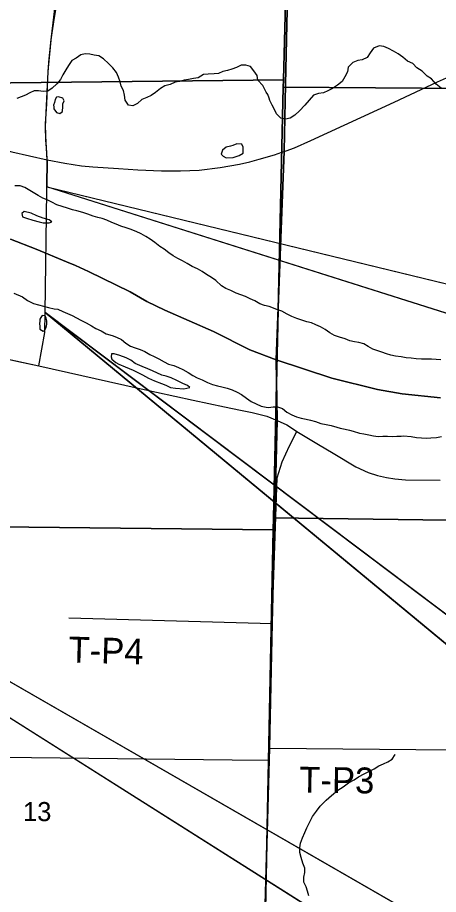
# Model space of a CAD drawing. Extents: x -6.2 to 37.4, y 0.2 to 22.2.
# Drawn here: x 6.554 to 7.016, y 18.086 to 19.048 of the extents above; entities that cross this region are included whole.
import ezdxf

# ---------------------------------------------------------------- set-up
doc = ezdxf.new("R2010")
doc.units = 0
for name, color, linetype in [('GM_X_County_Road', 7, 'Continuous'), ('GM_X_Major_River', 7, 'Continuous'), ('GM_X_Minor_Lake', 7, 'Continuous'), ('GM_X_Minor_River', 7, 'Continuous'), ('GM_X_Rail_Line', 7, 'Continuous'), ('GM_X_Section', 7, 'Continuous'), ('GM_X_Section_Text', 7, 'Continuous'), ('GM_X_State_Route', 7, 'Continuous'), ('GM_X_Township_Road', 7, 'Continuous'), ('GM_X_Township_Road_Text', 7, 'Continuous'), ('SH_Border', 7, 'Continuous'), ('SH_Data', 7, 'Continuous')]:
    doc.layers.add(name, color=color, linetype=linetype)

msp = doc.modelspace()

# ---------------------------------------------------------------- linework, layer by layer
at = {"layer": 'GM_X_County_Road'}
msp.add_line((6.83037, 18.23311), (6.83074, 18.24628), dxfattribs=at)
for points in [[(6.84422, 18.90029), (6.8466, 18.90115), (6.84894, 18.90199), (6.85783, 18.90517), (6.87593, 18.91318), (6.96728, 18.95529), (7.01486, 18.97759), (7.04447, 18.9907), (7.06641, 18.99975), (7.0938, 19.00981), (7.11336, 19.01664), (7.12764, 19.02142), (7.2025, 19.04605), (7.25814, 19.06492)], [(5.74614, 19.00637), (5.76053, 19.00771), (5.82808, 19.01396), (5.84969, 19.01583), (5.87667, 19.01703), (5.90748, 19.01824), (5.97635, 19.01934), (6.0098, 19.01912), (6.03809, 19.01824), (6.06299, 19.01681), (6.09907, 19.01363), (6.13043, 19.00979), (6.17144, 19.00354), (6.20643, 18.99707), (6.23648, 18.99115), (6.25369, 18.98775), (6.27497, 18.98271), (6.29986, 18.97591), (6.348, 18.96099), (6.4013, 18.944), (6.45745, 18.92634), (6.50088, 18.91318), (6.5477, 18.9009), (6.58673, 18.89193)], [(6.63664, 18.88445), (6.6649, 18.88242), (6.68601, 18.88108), (6.71198, 18.88006), (6.73293, 18.87995), (6.75354, 18.88083), (6.77657, 18.88357), (6.79752, 18.88719), (6.80907, 18.88975), (6.81934, 18.89256), (6.83612, 18.89739), (6.84422, 18.90029)], [(6.58673, 18.89193), (6.60586, 18.88829), (6.62412, 18.8856), (6.63664, 18.88445)], [(6.83074, 18.24628), (6.83341, 18.38304), (6.83905, 18.543), (6.84454, 18.56037), (6.8526, 18.57816), (6.86065, 18.59398)], [(6.81857, 17.70742), (6.81923, 17.74059), (6.82357, 17.99459), (6.83037, 18.23311)]]:
    msp.add_lwpolyline(points, dxfattribs=at)
at = {"layer": 'GM_X_Major_River'}
msp.add_line((6.57082, 18.82573), (6.57798, 18.82388), dxfattribs=at)
for points in [[(6.83003, 18.731), (6.82494, 18.73205), (6.81987, 18.73386), (6.81426, 18.73719), (6.8092, 18.73957), (6.80433, 18.74194), (6.79907, 18.74376), (6.79399, 18.74557), (6.788, 18.74853), (6.78275, 18.75072), (6.7777, 18.75386), (6.77177, 18.75967), (6.76691, 18.7628), (6.7615, 18.76633), (6.75664, 18.76927), (6.7514, 18.77222), (6.74578, 18.77499), (6.74017, 18.77814), (6.73493, 18.78128), (6.72988, 18.78384), (6.72502, 18.78679), (6.72017, 18.79011), (6.71514, 18.794), (6.71009, 18.79695), (6.70469, 18.80123), (6.69965, 18.80475), (6.69479, 18.80769), (6.68956, 18.81083), (6.68431, 18.8134), (6.67763, 18.81576), (6.67323, 18.81742), (6.66759, 18.81924), (6.66213, 18.82139), (6.65763, 18.82336), (6.65202, 18.82581), (6.64678, 18.82757), (6.64205, 18.82867), (6.63697, 18.83029), (6.63115, 18.8323), (6.62589, 18.83411), (6.6193, 18.83595), (6.6144, 18.83719), (6.60895, 18.83882), (6.60312, 18.84083), (6.59729, 18.84265), (6.59187, 18.84561), (6.58662, 18.84818), (6.5819, 18.84986), (6.57669, 18.85293), (6.56211, 18.86176), (6.55685, 18.86338), (6.55117, 18.86331)], [(6.57798, 18.82388), (6.58212, 18.82285), (6.58874, 18.82291), (6.59179, 18.82398), (6.58882, 18.82632), (6.58204, 18.82816), (6.57528, 18.83057), (6.56909, 18.83336), (6.56137, 18.83522), (6.55868, 18.83318), (6.55954, 18.82937), (6.56406, 18.82796), (6.57082, 18.82573)], [(6.55003, 18.74572), (6.55971, 18.74151), (6.56519, 18.73744), (6.57175, 18.73428), (6.57702, 18.73284), (6.58248, 18.73141), (6.58793, 18.72978), (6.59444, 18.72864), (6.59849, 18.72805), (6.60374, 18.72548), (6.61387, 18.7211), (6.62361, 18.71616), (6.62941, 18.71301), (6.63521, 18.70967)], [(6.98612, 18.67419), (6.98044, 18.67466), (6.97496, 18.67569), (6.96891, 18.67636), (6.96381, 18.67777), (6.95891, 18.67918), (6.95381, 18.68077), (6.94841, 18.68273), (6.94383, 18.68436), (6.93895, 18.68709), (6.93388, 18.69021), (6.9286, 18.69162), (6.92368, 18.69227), (6.91858, 18.69349), (6.91349, 18.69547), (6.90746, 18.69728), (6.90199, 18.69926), (6.89674, 18.70219), (6.89168, 18.70569), (6.88642, 18.70881), (6.88133, 18.71079), (6.87644, 18.71296), (6.87154, 18.71437), (6.86588, 18.71598), (6.86041, 18.71777), (6.85514, 18.72013), (6.84988, 18.72269), (6.84405, 18.72582), (6.83859, 18.7278), (6.83003, 18.731)], [(6.63521, 18.70967), (6.63988, 18.70705), (6.64588, 18.70415), (6.65149, 18.70119), (6.65789, 18.69935), (6.66277, 18.69736), (6.66802, 18.69479), (6.67285, 18.69071), (6.67809, 18.68757), (6.68315, 18.68557), (6.6888, 18.68394), (6.69367, 18.68156), (6.69906, 18.6782), (6.70416, 18.67623), (6.70921, 18.67366), (6.71501, 18.67013), (6.71988, 18.66776), (6.72553, 18.66632), (6.73059, 18.66394), (6.73547, 18.66194), (6.74126, 18.6586), (6.74631, 18.65547), (6.75117, 18.6529), (6.75669, 18.65063), (6.76261, 18.64755), (6.76805, 18.64536), (6.77351, 18.64392), (6.77841, 18.64287), (6.78406, 18.64143), (6.7895, 18.63942), (6.79494, 18.63685), (6.79981, 18.63429), (6.80521, 18.63038), (6.81044, 18.62686), (6.816, 18.62432), (6.8215, 18.62171), (6.82696, 18.62065), (6.82955, 18.62016)], [(7.01852, 18.67252), (7.01322, 18.67299), (7.0081, 18.67307), (7.00204, 18.67336), (6.99711, 18.67325), (6.99142, 18.67353), (6.98612, 18.67419)], [(6.82955, 18.62016), (6.8345, 18.62084), (6.83943, 18.62095), (6.8447, 18.61897), (6.84957, 18.6151), (6.85501, 18.61197), (6.86028, 18.6098), (6.86519, 18.60858), (6.87067, 18.60735), (6.87558, 18.60633), (6.88086, 18.60472), (6.88689, 18.60273), (6.89256, 18.6015), (6.89804, 18.60046), (6.90431, 18.59855), (6.90823, 18.59745), (6.91352, 18.59641), (6.91843, 18.5952), (6.92222, 18.59414), (6.92918, 18.59218), (6.9341, 18.59115), (6.93958, 18.5903), (6.94449, 18.58908), (6.94978, 18.58824), (6.9549, 18.58854), (6.95984, 18.58884), (6.96514, 18.58837), (6.97008, 18.58867), (6.97482, 18.58879), (6.97766, 18.58903), (6.98581, 18.58842), (6.99167, 18.58737), (6.99734, 18.58671), (7.00265, 18.58663), (7.00739, 18.58674), (7.01366, 18.58721), (7.01936, 18.58825)]]:
    msp.add_lwpolyline(points, dxfattribs=at)
at = {"layer": 'GM_X_Minor_Lake'}
for p, q in [((6.59454, 18.95501), (6.59372, 18.95218)), ((6.79019, 18.90765), (6.78791, 18.90712)), ((6.57873, 18.71498), (6.5783, 18.71252)), ((6.69105, 18.656), (6.6976, 18.65227))]:
    msp.add_line(p, q, dxfattribs=at)
for points in [[(6.59372, 18.95218), (6.59405, 18.95009), (6.59382, 18.94782), (6.59695, 18.94377), (6.60053, 18.94294), (6.6036, 18.94515), (6.60391, 18.95065), (6.60396, 18.95331), (6.60517, 18.95688), (6.60372, 18.95976), (6.5992, 18.96099), (6.59674, 18.96066), (6.59536, 18.95822), (6.59454, 18.95501)], [(6.78791, 18.90712), (6.78315, 18.90589), (6.77892, 18.90256), (6.77751, 18.89823), (6.77954, 18.89591), (6.7831, 18.89432), (6.79049, 18.89474), (6.79716, 18.8967), (6.80157, 18.89945), (6.8017, 18.9059), (6.80007, 18.90916), (6.79478, 18.90964), (6.79019, 18.90765)], [(6.5783, 18.71252), (6.57841, 18.70891), (6.57854, 18.70607), (6.58022, 18.70489), (6.58228, 18.7039), (6.58362, 18.70483), (6.58519, 18.70726), (6.586, 18.7099), (6.58642, 18.71179), (6.58611, 18.71521), (6.58542, 18.71807), (6.58453, 18.72074), (6.58112, 18.721), (6.57957, 18.71895), (6.57839, 18.71707), (6.57873, 18.71498)], [(6.6976, 18.65227), (6.70435, 18.64929), (6.71187, 18.64667), (6.71675, 18.64468), (6.72199, 18.64211), (6.72747, 18.64143), (6.73672, 18.64067), (6.743, 18.64206), (6.74058, 18.6442), (6.73552, 18.64658), (6.72878, 18.64975), (6.72278, 18.65271), (6.71714, 18.65453), (6.71225, 18.65577), (6.70231, 18.66052), (6.69687, 18.66272), (6.69087, 18.66511), (6.68318, 18.66849), (6.67833, 18.67201), (6.67328, 18.67476), (6.66651, 18.67718), (6.65993, 18.67901), (6.65709, 18.67926), (6.65683, 18.67566), (6.65772, 18.67318), (6.662, 18.66949), (6.66537, 18.66771), (6.67212, 18.66492), (6.68113, 18.66133), (6.686, 18.65876), (6.69105, 18.656)]]:
    msp.add_lwpolyline(points, dxfattribs=at)
at = {"layer": 'GM_X_Minor_River'}
for points in [[(7.01903, 18.97063), (7.01322, 18.9749), (7.0084, 18.98086), (7.00352, 18.98398), (6.99792, 18.98938), (6.9923, 18.99289), (6.98764, 18.9979), (6.98199, 19.00026), (6.97676, 19.00452), (6.97152, 19.0084), (6.96663, 19.01114), (6.96118, 19.01407), (6.95611, 19.01643), (6.95081, 19.01728), (6.94451, 19.01472), (6.94101, 19.00946), (6.93751, 19.0044), (6.93216, 19.00183), (6.92741, 19.00115), (6.92187, 18.99877), (6.91685, 18.99354), (6.91601, 18.98862), (6.91326, 18.98316), (6.91014, 18.97789), (6.90495, 18.97399), (6.89958, 18.97047), (6.89461, 18.9679), (6.88965, 18.9657), (6.88413, 18.96465), (6.87898, 18.96284), (6.87396, 18.95741), (6.86913, 18.95218), (6.86333, 18.94563)], [(6.83001, 18.95964), (6.82861, 18.96372), (6.82671, 18.96643), (6.82319, 18.97376), (6.81782, 18.97956), (6.81716, 18.9845), (6.81348, 18.98951), (6.80961, 18.99433), (6.80472, 18.99595), (6.79942, 18.99586), (6.79445, 18.99331), (6.7893, 18.99151), (6.78435, 18.99009), (6.7794, 18.98886), (6.77462, 18.98668), (6.7697, 18.9864), (6.76325, 18.98596), (6.75813, 18.9855), (6.75219, 18.98201), (6.74707, 18.98117), (6.74175, 18.98032), (6.7368, 18.97929), (6.73186, 18.97806), (6.72711, 18.97739), (6.72157, 18.97485), (6.71586, 18.97307), (6.71106, 18.97013), (6.70549, 18.96607), (6.70069, 18.96275), (6.69591, 18.96057), (6.69057, 18.9584), (6.68555, 18.95376), (6.68058, 18.95139), (6.67567, 18.95206), (6.672, 18.95763), (6.67136, 18.96315), (6.67052, 18.96809), (6.66797, 18.97289), (6.66674, 18.97766), (6.66496, 18.98281), (6.66279, 18.98779), (6.65854, 18.99281), (6.65392, 18.99783), (6.64853, 19.00287), (6.6433, 19.00601), (6.63821, 19.00706), (6.63331, 19.00811), (6.62821, 19.0084), (6.62345, 19.00736), (6.61846, 19.00366), (6.61367, 19.00091), (6.60996, 18.99568), (6.60702, 18.9908), (6.60368, 18.98518), (6.60131, 18.9803), (6.59704, 18.97545), (6.59222, 18.9708), (6.58741, 18.96729), (6.58229, 18.96683), (6.5772, 18.96769), (6.57228, 18.96779), (6.5675, 18.96561), (6.56271, 18.96286), (6.55794, 18.96106), (6.55318, 18.95944)], [(6.86333, 18.94563), (6.85832, 18.94097), (6.85315, 18.93763), (6.84801, 18.93677), (6.84291, 18.9378), (6.83806, 18.94243), (6.83606, 18.94721), (6.83348, 18.95199), (6.83092, 18.95716), (6.83001, 18.95964)], [(6.87373, 18.08413), (6.8723, 18.08928), (6.87068, 18.09424), (6.8683, 18.0994), (6.8682, 18.10472), (6.86943, 18.10982), (6.86932, 18.11457), (6.86713, 18.11992), (6.86515, 18.12621), (6.86373, 18.13174), (6.86363, 18.13686), (6.86448, 18.14216), (6.86666, 18.14782), (6.86922, 18.15366), (6.87159, 18.15893), (6.87434, 18.16458), (6.87787, 18.17136), (6.88213, 18.17717), (6.88621, 18.1828), (6.89276, 18.18914), (6.89854, 18.19436), (6.90565, 18.20013), (6.91141, 18.20402), (6.91735, 18.2081), (6.92329, 18.21161), (6.92828, 18.21495), (6.93421, 18.21827), (6.93937, 18.22065), (6.94549, 18.22378), (6.95047, 18.22692), (6.95544, 18.22912), (6.96021, 18.23113), (6.96501, 18.23428), (6.9685, 18.23935), (6.96831, 18.23916)]]:
    msp.add_lwpolyline(points, dxfattribs=at)
at = {"layer": 'GM_X_Rail_Line'}
for points in [[(6.54632, 18.80482), (6.57464, 18.79409), (6.60765, 18.78021), (6.61783, 18.77607), (6.63207, 18.76934), (6.67768, 18.74711), (6.6958, 18.73663), (6.71582, 18.72697), (6.76905, 18.70361), (6.80885, 18.68332), (6.83768, 18.67262), (6.84649, 18.90142), (6.84823, 18.97455), (6.85392, 19.23765), (6.86, 19.46814), (6.86031, 19.48424), (6.86039, 19.48824), (6.86049, 19.49225), (6.86104, 19.5138), (6.86366, 19.68706)], [(6.85392, 19.23765), (6.84823, 18.97455), (6.84649, 18.90142), (6.83768, 18.67262), (6.89882, 18.65237), (6.94894, 18.63998), (6.97623, 18.6353), (7.018, 18.63095)], [(5.08086, 17.70742), (6.81845, 17.70742), (6.81912, 17.74087), (6.82345, 17.99486), (6.83025, 18.23339), (6.83063, 18.24656), (6.8333, 18.38332), (6.83898, 18.60604), (6.83768, 18.67262), (6.80885, 18.68332), (6.76905, 18.70361), (6.71582, 18.72697), (6.6958, 18.73663), (6.67768, 18.74711), (6.63207, 18.76934), (6.61783, 18.77607), (6.60765, 18.78021), (6.57464, 18.79409), (6.54632, 18.80482)], [(7.018, 18.63095), (6.97623, 18.6353), (6.94894, 18.63998), (6.89882, 18.65237), (6.83768, 18.67262), (6.83898, 18.60604), (6.8333, 18.38332), (6.83063, 18.24656), (6.83025, 18.23339), (6.82345, 17.99486)]]:
    msp.add_lwpolyline(points, dxfattribs=at)
at = {"layer": 'GM_X_Section'}
for points in [[(6.35528, 19.47792), (6.85879, 19.4746), (6.84574, 18.97965), (6.34692, 18.97447)], [(6.85879, 19.4746), (7.36, 19.47055), (7.35203, 18.96803), (6.8456, 18.97191), (6.84574, 18.97965)], [(6.34692, 18.97447), (6.84574, 18.97965), (6.8456, 18.97191), (6.83509, 18.49918), (6.83443, 18.48586), (6.33154, 18.49141)], [(7.35203, 18.96803), (7.35041, 18.87769), (7.33152, 18.7501), (7.32687, 18.49251), (6.83509, 18.49918), (6.8456, 18.97191)], [(6.83509, 18.49918), (7.32687, 18.49251), (7.32438, 17.99011), (7.32268, 17.99032), (6.89968, 17.99325), (6.82474, 17.99671), (6.83443, 18.48586)], [(6.33154, 18.49141), (6.83443, 18.48586), (6.82474, 17.99671), (6.82431, 17.98462), (6.31963, 17.9903)]]:
    msp.add_lwpolyline(points, close=True, dxfattribs=at)
at = {"layer": 'GM_X_State_Route'}
msp.add_line((6.58622, 18.86242), (6.58673, 18.89193), dxfattribs=at)
for points in [[(6.58673, 18.89193), (6.58619, 18.90046), (6.5851, 18.91362), (6.58477, 18.9282), (6.58674, 18.96648), (6.58729, 18.98172), (6.58839, 18.99927), (6.59091, 19.02405), (6.59475, 19.0484), (6.59751, 19.06517), (6.59937, 19.07975), (6.60067, 19.09665), (6.60163, 19.11807)], [(6.58436, 18.72432), (6.58613, 18.8575), (6.58622, 18.86242)], [(6.57753, 18.66574), (6.58407, 18.70261), (6.58436, 18.72432)], [(6.33938, 18.70845), (6.3672, 18.70504), (6.43193, 18.69677), (6.44972, 18.69366), (6.49481, 18.68405), (6.55344, 18.67091), (6.57753, 18.66574)], [(6.57753, 18.66574), (6.68642, 18.64144), (6.74681, 18.62821), (6.78114, 18.62107), (6.79865, 18.61739)], [(6.79865, 18.61739), (6.81165, 18.61466), (6.82758, 18.61062), (6.8391, 18.60577), (6.8495, 18.60101), (6.86015, 18.59429), (6.86065, 18.59398)], [(6.86065, 18.59398), (6.88435, 18.5794), (6.90048, 18.56988), (6.9254, 18.5552), (6.93864, 18.54899), (6.94908, 18.54558), (6.95901, 18.5432), (6.96801, 18.54186), (6.9799, 18.54093), (7.01774, 18.54031)]]:
    msp.add_lwpolyline(points, dxfattribs=at)
at = {"layer": 'GM_X_Township_Road'}
for p, q in [((6.61041, 18.3894), (6.83341, 18.38304)), ((6.83037, 18.23311), (6.83074, 18.24628))]:
    msp.add_line(p, q, dxfattribs=at)
for points in [[(5.82441, 18.24572), (6.06888, 18.24224), (6.32489, 18.23861), (6.53809, 18.2365), (6.78956, 18.23331), (6.83037, 18.23311)], [(6.83074, 18.24628), (7.03135, 18.24461), (7.20052, 18.24234)]]:
    msp.add_lwpolyline(points, dxfattribs=at)
at = {"layer": 'SH_Border'}
for p, q in [((6.58622, 18.86242), (8.99438, 18.27767)), ((8.99438, 18.09947), (6.58622, 18.86242)), ((5.83681, 18.72749), (8.99438, 16.9093)), ((8.99438, 16.73109), (5.83681, 18.72749)), ((6.58436, 18.72432), (8.99438, 16.9093)), ((8.99438, 16.73109), (6.58436, 18.72432))]:
    msp.add_line(p, q, dxfattribs=at)
at = {"layer": 'SH_Data'}
msp.add_line((6.58673, 18.89193), (6.58622, 18.86242), dxfattribs=at)
for points in [[(6.58673, 18.89193), (6.585, 18.91781), (6.58494, 18.93144), (6.58606, 18.95329), (6.58777, 18.98936), (6.59138, 19.027), (6.60143, 19.11367), (6.60488, 19.26038)], [(5.83681, 18.72749), (5.84854, 18.72859), (5.93767, 18.73698), (5.96065, 18.73827), (5.98286, 18.73794), (6.02592, 18.7348), (6.06332, 18.73152), (6.24199, 18.71179), (6.29634, 18.70995), (6.33657, 18.70855), (6.3844, 18.70284), (6.43307, 18.69657), (6.45738, 18.69203), (6.48501, 18.68614), (6.51494, 18.67954), (6.57753, 18.66574)], [(6.57753, 18.66574), (6.58407, 18.70261), (6.58436, 18.72432)]]:
    msp.add_lwpolyline(points, dxfattribs=at)
for points in [[(8.99438, 18.09947), (6.58622, 18.86242), (8.99438, 18.27767)], [(8.99438, 16.73109), (5.83681, 18.72749), (8.99438, 16.9093)], [(8.99438, 16.9093), (6.58436, 18.72432), (8.99438, 16.73109)]]:
    msp.add_lwpolyline(points, close=True, dxfattribs=at)

# ---------------------------------------------------------------- texts
at = {"layer": 'GM_X_Section_Text'}
msp.add_text('13', height=0.020928, rotation=0.00001, dxfattribs=at).set_placement((6.5601, 18.16622))
at = {"layer": 'GM_X_Township_Road_Text'}
for s, rotation, p in [('T-P4', 358.2847, (6.60967, 18.34044)), ('T-P3', 359.31423, (6.86305, 18.19751))]:
    msp.add_text(s, height=0.028409, rotation=rotation, dxfattribs=at).set_placement(p)

doc.saveas('drawing.dxf')
